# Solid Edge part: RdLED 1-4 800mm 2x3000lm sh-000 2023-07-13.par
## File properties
Author: robert.pupel
Template: iso metric part.par
Last saved by: robert.pupel
Revision: 2
Application: Solid Edge
Gęstość: 0.000 kg/m^3
Dokładność: 0.990
Username: robert.pupel
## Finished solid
Body 1: solid body, 8880 faces, 23050 edges, 14996 vertices.
  Faces by surface: plane 6908, cylinder 940, torus 416, cone 352, spline 184, sphere 80
  Edges by curve: line 18762, curve on surface 2488, circle 1024, ellipse 528, spline 248
Bounding box of the edges (mm; curved faces can reach further): 395.929 x 4.450 x 395.929, from (-197.9647, -3.45, -197.9647) to (197.9647, 1, 197.9647).
Cylindrical faces by radius (mm): R0.199 x8, R0.2 x312, R0.2002 x16, R0.2169 x24, R0.25 x96, R0.3 x16, R0.3373 x24, R0.4 x64, R0.4006 x16, R0.4008 x16, R0.525 x16, R0.6 x96, R1 x56, R1.0894 x16, R1.0991 x32, R1.1 x112, R2.15 x16, R2.5 x3, R401 x1
Conical faces (half-angle, radius in mm at the cone's reference point): 0.3913 deg R1.0968 x16, 0.447 deg R1.0952 x16, 0.464 deg R1.0955 x16, 0.5 deg R0.5056 x32, 0.5 deg R1.0082 x32, 1 deg R0.5511 x16, 10 deg R0.2132 x16, 10 deg R0.4132 x16, 15.6748 deg R1.1041 x8, 15.6751 deg R1.1041 x8, 15.7937 deg R1.1267 x8, 15.7938 deg R1.1267 x8, 18.4844 deg R1.0657 x32, 18.9316 deg R0.5099 x16, 19.4337 deg R0.5111 x16, 27.363 deg R0.6214 x16, 40.1968 deg R0.519 x8, 40.228 deg R0.5176 x8, 42.9179 deg R0.4919 x8, 42.9331 deg R0.4916 x8, 45 deg R0.575 x16, 45 deg R0.625 x32
Toroidal faces (ring radius, tube radius in mm): R0.0958 r0.3997 x32, R0.1 r0.2 x8, R0.1075 r0.4 x16, R0.1101 r0.4001 x16, R0.1216 r0.4 x16, R0.1234 r0.4 x16, R0.1634 r0.2287 x8, R0.1641 r0.2287 x8, R0.3286 r0.2001 x8, R0.3702 r0.4 x16, R0.3818 r0.2 x16, R0.4163 r0.3984 x16, R0.4824 r0.2001 x8, R0.4952 r0.2 x8, R0.6008 r0.3968 x16, R0.6009 r0.3969 x16, R0.6227 r0.2 x8, R0.6235 r0.2 x8, R0.8 r0.2 x32, R0.8522 r0.3 x16, R0.9002 r0.2 x8, R0.9018 r0.2 x8, R0.9181 r0.2227 x16, R0.9197 r0.223 x8, R0.9199 r0.223 x8, R0.9663 r0.2263 x8, R0.9665 r0.2263 x8, R1.3 r0.2 x16, R1.327 r1.1 x16, R1.3271 r1.1 x16, R1.8741 r0.2175 x8, R1.8987 r0.2 x8
Spherical faces by radius (mm): R0.2 x64, R0.6 x16
Planar faces by outward normal: +x 119, +y 57, +z 84, -x 82, -y 1209, -z 119, oblique 5238
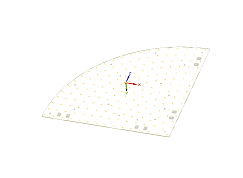
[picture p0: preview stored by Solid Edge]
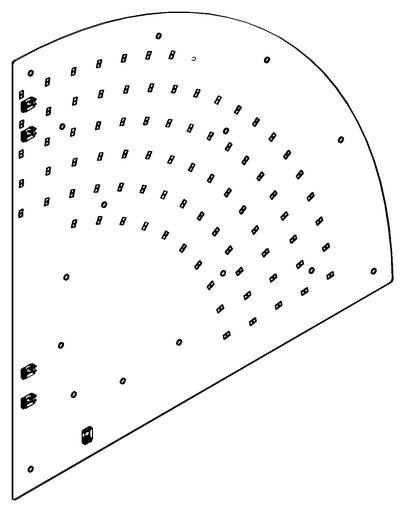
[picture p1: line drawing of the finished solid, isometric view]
